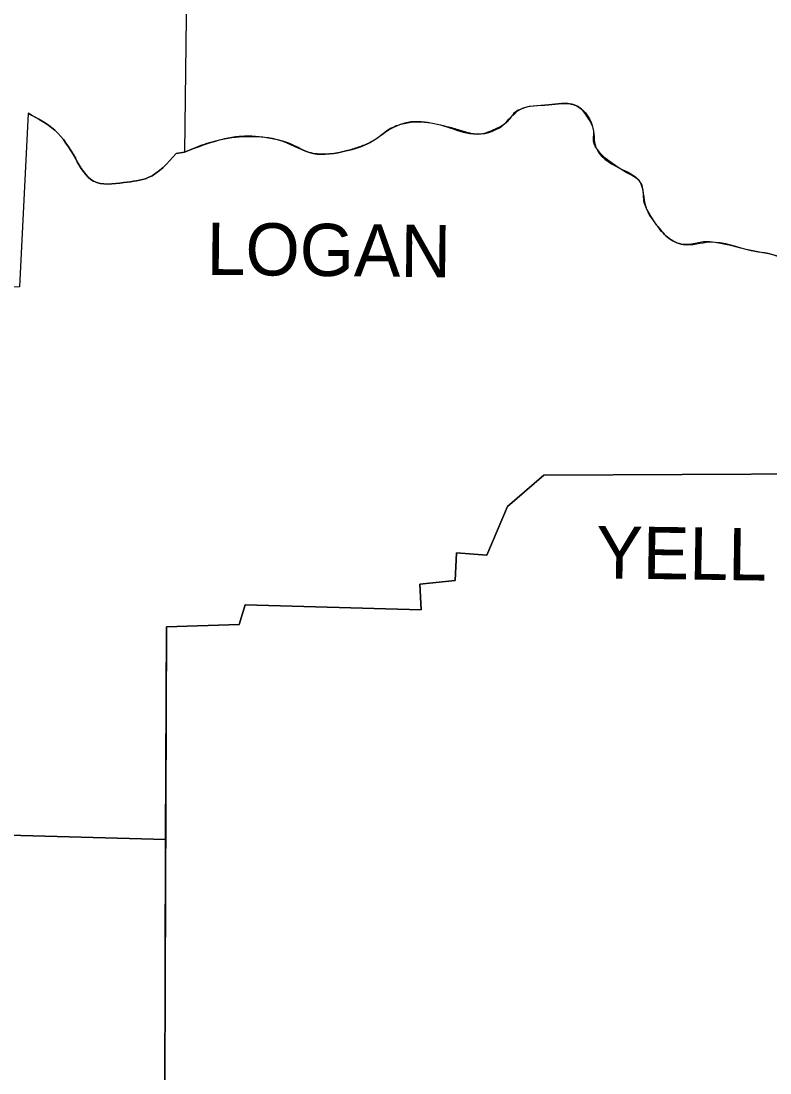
# Model space of a CAD drawing. Extents: x -13171 to 18763, y -8840 to 11152.
# Drawn here: x 11711 to 12315, y 7898 to 8746 of the extents above; entities that cross this region are included whole.
import ezdxf

# ---------------------------------------------------------------- set-up
doc = ezdxf.new("R2010")
doc.units = 0
for name, color, linetype in [('Level 1', 7, 'Continuous'), ('Level 2', 7, 'Continuous'), ('Level 48', 7, 'Continuous')]:
    doc.layers.add(name, color=color, linetype=linetype)

msp = doc.modelspace()

# ---------------------------------------------------------------- linework, layer by layer
at = {"layer": 'Level 1'}
msp.add_line((11836.314181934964, 8638.934206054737), (11843.163029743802, 8639.912612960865), dxfattribs=at)
for points in [[(11850.011877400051, 9204.453346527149), (11843.163029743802, 8639.912612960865)], [(11716.948550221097, 8671.221631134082), (11710.099702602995, 8531.309456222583), (11582.906816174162, 8530.331049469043), (11576.057968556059, 8403.138163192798), (11449.843489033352, 8406.073383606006), (11445.929861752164, 8274.966870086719), (11313.844941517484, 8273.988463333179), (11309.931314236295, 8142.881949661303), (11393.095893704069, 8137.989915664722), (11390.160673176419, 8097.875236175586), (11827.900316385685, 8085.771835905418)], [(12355.84820201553, 8380.634806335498), (12132.771447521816, 8379.656399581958), (12103.419243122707, 8354.21782231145), (12086.786327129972, 8315.081549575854), (12062.326156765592, 8317.038363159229), (12061.347749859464, 8294.535006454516), (12032.973952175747, 8291.59978588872), (12033.952359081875, 8271.053242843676), (11892.083370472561, 8274.966870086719), (11887.191336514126, 8259.312360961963), (11828.486927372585, 8257.35554737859), (11826.530113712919, 7684.987559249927), (11777.609772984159, 7684.009152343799), (11781.52340011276, 7654.656947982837), (11734.559872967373, 7655.635354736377), (11733.581466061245, 7634.110404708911), (11687.5963456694, 7634.110404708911), (11688.574752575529, 7618.455895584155), (11620.086275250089, 7616.499081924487), (11619.107868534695, 7556.816266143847), (11552.576204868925, 7562.686707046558), (11541.813729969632, 7081.31055302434), (11165.12710525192, 7082.2889597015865), (11156.32144397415, 6970.7505825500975)]]:
    msp.add_lwpolyline(points, dxfattribs=at)
for points in [[(11843.163029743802, 8639.912612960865), (11875.45045467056, 8650.67508793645), (11898.932218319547, 8652.631901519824), (11922.413981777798, 8648.718274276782), (11946.874152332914, 8638.934206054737), (11973.291136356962, 8640.891019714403), (11992.85927272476, 8647.739867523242), (12012.427409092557, 8660.459156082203), (12033.952359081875, 8664.372783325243), (12054.498902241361, 8660.459156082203), (12076.023852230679, 8654.588715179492), (12099.50561584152, 8661.43756298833), (12113.203311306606, 8674.15685154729), (12136.685074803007, 8678.070478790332), (12157.231618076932, 8678.070478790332), (12171.907720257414, 8661.43756298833), (12174.84294082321, 8643.826240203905), (12193.432670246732, 8627.193324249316), (12210.065586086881, 8616.430849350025), (12214.957620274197, 8595.884306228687), (12223.763281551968, 8581.20820385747), (12232.568943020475, 8571.424135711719), (12245.288231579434, 8565.553694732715), (12266.813181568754, 8567.510508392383), (12300.079013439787, 8560.661660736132), (12321.603963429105, 8555.769626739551), (12341.172099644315, 8539.13671078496), (12359.761829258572, 8521.525388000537)], [(11716.948550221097, 8671.221631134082), (11738.473500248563, 8657.523935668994), (11755.106416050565, 8635.020578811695), (11769.78251842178, 8616.430849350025), (11794.242688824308, 8615.452442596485), (11813.810825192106, 8619.366069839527), (11836.314181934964, 8638.934206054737)]]:
    msp.add_spline(points, degree=3, dxfattribs=at)
at = {"layer": 'Level 48'}
for p, q in [((11843.163029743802, 8639.912612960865), (11836.314181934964, 8638.934206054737)), ((12086.786327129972, 8315.081549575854), (12103.419243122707, 8354.21782231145)), ((12061.347749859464, 8294.535006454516), (12062.326156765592, 8317.038363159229)), ((12062.326156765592, 8317.038363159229), (12086.786327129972, 8315.081549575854)), ((11887.191336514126, 8259.312360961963), (11892.083370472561, 8274.966870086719)), ((11892.083370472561, 8274.966870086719), (12033.952359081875, 8271.053242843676)), ((11827.900316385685, 8085.771835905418), (11826.530113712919, 7684.987559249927)), ((11826.530113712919, 7684.987559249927), (11827.900316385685, 8085.771835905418))]:
    msp.add_line(p, q, dxfattribs=at)
for points in [[(11716.948550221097, 8671.221631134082), (11710.099702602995, 8531.309456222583), (11582.906816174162, 8530.331049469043), (11576.057968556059, 8403.138163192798), (11449.843489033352, 8406.073383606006), (11449.011843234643, 8378.213249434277)], [(12359.761829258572, 8521.525388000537), (12355.84820201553, 8380.634806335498), (12132.771447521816, 8379.656399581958), (12103.419243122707, 8354.21782231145), (12086.786327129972, 8315.081549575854), (12062.326156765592, 8317.038363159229), (12061.347749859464, 8294.535006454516), (12032.973952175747, 8291.59978588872), (12033.952359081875, 8271.053242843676), (11892.083370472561, 8274.966870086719), (11887.191336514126, 8259.312360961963), (11828.486927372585, 8257.35554737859), (11827.900316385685, 8085.771835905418)], [(12103.419243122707, 8354.21782231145), (12132.771447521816, 8379.656399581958), (12355.84820201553, 8380.634806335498), (12359.761829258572, 8521.525388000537)], [(11827.900316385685, 8085.771835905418), (11390.160673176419, 8097.875236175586), (11393.095893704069, 8137.989915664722), (11309.931314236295, 8142.881949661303), (11312.325830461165, 8223.098243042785), (11313.844941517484, 8273.988463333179), (11445.929861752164, 8274.966870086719), (11449.011843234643, 8378.213249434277)], [(12033.952359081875, 8271.053242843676), (12032.973952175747, 8291.59978588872), (12061.347749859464, 8294.535006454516)], [(11827.900316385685, 8085.771835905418), (11828.486927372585, 8257.35554737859), (11887.191336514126, 8259.312360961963)], [(11393.095893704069, 8137.989915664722), (11390.160673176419, 8097.875236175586), (11827.900316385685, 8085.771835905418)]]:
    msp.add_lwpolyline(points, dxfattribs=at)
for points in [[(12329.114490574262, 8551.20243986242), (12321.603963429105, 8555.769626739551), (12310.91566817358, 8558.639119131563), (12300.079013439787, 8560.661660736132), (12266.813181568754, 8567.510508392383), (12261.473826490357, 8567.631179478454), (12256.077744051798, 8566.639145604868), (12250.668142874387, 8565.593589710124), (12245.288231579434, 8565.553694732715), (12232.568943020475, 8571.424135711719), (12223.763281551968, 8581.20820385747), (12219.058710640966, 8588.43034832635), (12216.953924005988, 8592.132956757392), (12214.957620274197, 8595.884306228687), (12213.516036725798, 8600.955689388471), (12213.119763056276, 8606.464574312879), (12212.419409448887, 8611.819960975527), (12210.065586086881, 8616.430849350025), (12208.261658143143, 8618.178220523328), (12206.286113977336, 8619.674661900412), (12202.006159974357, 8622.186865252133), (12197.597690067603, 8624.511679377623), (12193.432670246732, 8627.193324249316), (12174.84294082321, 8643.826240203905), (12173.146282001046, 8647.761102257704), (12172.986926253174, 8652.32111227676), (12173.021772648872, 8657.036516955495), (12171.907720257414, 8661.43756298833), (12169.152112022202, 8666.573161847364), (12165.990428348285, 8671.440553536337), (12162.11836508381, 8675.464678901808), (12157.231618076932, 8678.070478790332), (12154.678837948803, 8678.70238865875), (12152.113533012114, 8679.052592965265), (12146.961519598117, 8679.110204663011), (12136.685074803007, 8678.070478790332), (12113.203311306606, 8674.15685154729), (12109.345341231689, 8671.767770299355), (12106.316483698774, 8668.196166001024), (12103.306616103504, 8664.425082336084), (12099.50561584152, 8661.43756298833), (12093.654654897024, 8658.495649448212), (12087.79106270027, 8655.989609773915), (12081.914306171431, 8654.49533475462), (12076.023852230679, 8654.588715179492), (12070.657596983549, 8655.831982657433), (12065.299422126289, 8657.408942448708), (12059.922224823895, 8659.04339883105), (12054.498902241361, 8660.459156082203), (12033.952359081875, 8664.372783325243), (12023.187925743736, 8663.875894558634), (12017.803641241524, 8662.458353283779), (12012.427409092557, 8660.459156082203), (12007.149267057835, 8657.585419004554), (12002.450083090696, 8654.126112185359), (11997.84752803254, 8650.653505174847), (11992.85927272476, 8647.739867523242), (11983.23233915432, 8643.870108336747), (11973.291136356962, 8640.891019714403), (11960.043200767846, 8638.52371095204), (11946.874152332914, 8638.934206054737), (11940.688849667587, 8640.807815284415), (11934.692412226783, 8643.609529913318), (11928.671802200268, 8646.51959966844), (11922.413981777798, 8648.718274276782), (11910.711803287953, 8651.241368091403), (11898.932218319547, 8652.631901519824), (11887.186873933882, 8652.456639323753), (11875.45045467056, 8650.67508793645), (11867.131084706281, 8648.600591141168), (11859.001968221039, 8646.157567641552), (11843.163029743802, 8639.912612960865)], [(11836.314181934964, 8638.934206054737), (11813.810825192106, 8619.366069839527), (11794.242688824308, 8615.452442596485), (11769.78251842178, 8616.430849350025), (11755.106416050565, 8635.020578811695), (11738.473500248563, 8657.523935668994), (11716.948550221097, 8671.221631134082)]]:
    msp.add_spline(points, degree=3, dxfattribs=at)

# ---------------------------------------------------------------- texts
at = {"layer": 'Level 2'}
for s, rotation, p in [('LOGAN', 359.3969083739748, (11860.774352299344, 8541.093524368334)), ('YELL', 359.19871388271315, (12174.84294082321, 8296.491820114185))]:
    msp.add_text(s, height=42.07344995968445, rotation=rotation, dxfattribs=at).set_placement(p)

doc.saveas('drawing.dxf')
